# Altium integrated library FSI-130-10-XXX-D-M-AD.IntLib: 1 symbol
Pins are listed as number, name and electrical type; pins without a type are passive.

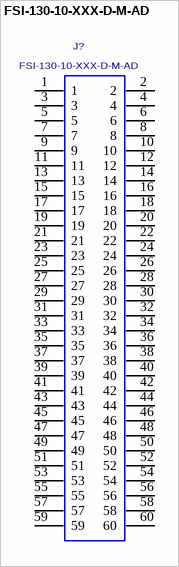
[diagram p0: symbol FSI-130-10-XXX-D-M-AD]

## FSI-130-10-XXX-D-M-AD
designator J?
Single Element Interface, Surface Mount, Top and Bottom Alignment Pins, Threaded insert,1mm Pitch, 60 Pins; MANUFACTURER: SAMTEC
footprint FSI-130-10-XXX-D-M-AD
pins: 1, 2, 3, 4, 5, 6, 7, 8, 9, 10, 11, 12, 13, 14, 15, 16, 17, 18, 19, 20, 21, 22, 23, 24, 25, 26, 27, 28, 29, 30, 31, 32, 33, 34, 35, 36, 37, 38, 39, 40, 41, 42, 43, 44, 45, 46, 47, 48, 49, 50, 51, 52, 53, 54, 55, 56, 57, 58, 59, 60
